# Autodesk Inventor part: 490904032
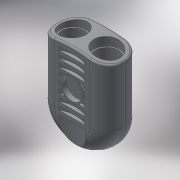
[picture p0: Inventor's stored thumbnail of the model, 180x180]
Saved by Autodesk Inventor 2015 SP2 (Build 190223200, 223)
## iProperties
Created: 2017-07
Part Number: 490904032
Material: Generic
Description: PLASSON 180° ELBOW 32
Document SubType Name: Modeling
Designer: Кирилл
Density: 1 g/cm^3
Appearance: Default
Author: Кирилл
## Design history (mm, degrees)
derived "490904.ipt"
feature "Solid1::490904.ipt"
tag "TaggingFeature1"
body "Solid1"
other parameters: "d0" = 88, "d1" = 108, "d2" = 21.6, "d3" = 8.8, "d4" = 86.4, "d5" = 52.8, "d6" = 44, "d7" = 0, "d8" = 32.4, "d9" = 32.4, "d10" = 19.8, "d11" = 2.2, "d12" = -21.6, "d13" = 17.6, "d14" = 35.2, "d15" = 32.4, "d16" = 0, "d17" = -4.32, "d18" = 4.32, "d19" = 0, "d22" = 8.64, "d23" = 30.8, "d24" = 64.8, "d26" = 0, "d27" = 26.4, "d28" = 5.5, "d29" = 0, "d30" = 0.44, "d31" = 0, "d32" = 32, "d33" = 32, "d34" = 44, "d35" = 22, "d36" = 41, "d37" = 0, "d38" = 35.2, "d39" = 35.2, "d40" = 10.25, "d41" = 0, "d42" = 28.8, "d43" = 180 deg, "d46" = 14, "d47" = 0, "d48" = 4, "d49" = 4.8, "d50" = 8, "d51" = 0, "d52" = 108, "d53" = 102.6, "d_" = 32, "L_" = 44, "L_1" = 41, "H_" = 108, "B_" = 88, "d_2" = 12
